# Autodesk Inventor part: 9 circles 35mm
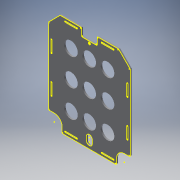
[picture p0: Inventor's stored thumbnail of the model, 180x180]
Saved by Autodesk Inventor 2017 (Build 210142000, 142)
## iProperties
Created: 2014-05
Part Number: 9 circles 35mm
Material: Generic
Document SubType Name: Modeling
Designer: Designer
Density: 1 g/cm^3
Appearance: Default
Author: Designer
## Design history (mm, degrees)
sketch "Sketch1" dims "d120" = 10, "d132" = 10
  geometry: L1 (97.5, 0)-(97.5, 10); L2 (82.5, 10)-(82.5, 0); L3 (17, 40)-(25, 40); L4 (25, 20)-(17, 20); L5 (15, 22)-(15, 38); L6 (195, 214.172)-(195, 22); L7 (158, -15)-(22, -15); L8 (-15, 22)-(-15, 214.172); L9 (-13, 20)-(0, 20); L10 (20, 0)-(20, -13); L11 (160, -13)-(160, 0); L12 (180, 20)-(193, 20); L13 (70, 243)-(70, 227); L14 (72, 225)-(108, 225); L15 (110, 227)-(110, 243); L16 (15, 245)-(-14.414, 215.586); L17 (165.586, 244.414)-(194.414, 215.586); L18 (15, 245)-(68, 245); L19 (112, 245)-(164.172, 245); L20 (27, 38)-(27, 22); C1 r 3 at (90, 220); C2 r 12.5 at (57.5, 177.5); C3 r 12.5 at (122.5, 177.5); C4 r 12.5 at (57.5, 115); C5 r 12.5 at (122.5, 115); C6 r 12.5 at (57.5, 52.5); C7 r 12.5 at (122.5, 52.5); A1 r 7.5 centre (90, 10) between (97.5, 10) and (82.5, 10); A2 r 20 centre (0, 0) between (20, 0) and (0, 20); A3 r 20 centre (180, 0) between (180, 20) and (160, 0); A4 r 7.5 centre (90, 0) between (82.5, 0) and (97.5, 0); A5 r 2 centre (17, 38) between (17, 40) and (15, 38); A6 r 2 centre (25, 22) between (25, 20) and (27, 22); A7 r 2 centre (17, 22) between (15, 22) and (17, 20); A8 r 2 centre (25, 38) between (27, 38) and (25, 40); A9 r 2 centre (68, 243) between (70, 243) and (68, 245); A10 r 2 centre (-13, 214.172) between (-14.414, 215.586) and (-15, 214.172); A11 r 2 centre (72, 227) between (70, 227) and (72, 225); A12 r 2 centre (108, 227) between (108, 225) and (110, 227); A13 r 2 centre (112, 243) between (112, 245) and (110, 243); A14 r 2 centre (164.172, 243) between (165.586, 244.414) and (164.172, 245); A15 r 2 centre (193, 214.172) between (195, 214.172) and (194.414, 215.586); A16 r 2 centre (193, 22) between (193, 20) and (195, 22); A17 r 2 centre (158, -13) between (158, -15) and (160, -13); A18 r 2 centre (22, -13) between (20, -13) and (22, -15); A19 r 2 centre (-13, 22) between (-15, 22) and (-13, 20); 19 further points
  constraints: 40 end point, 38 point on circle, 34 point on line, 34 tangent, 26 centre point, 11 equal radius, 11 perpendicular, 6 parallel, 4 horizontal, 1 vertical, 10 other
  dimensions: "d55" = 260 distance between parallel lines of L7 L19; "d56" = 210 distance between parallel lines of L6 L8; "d107" = 20 distance from line of C1.centre L13; "d111" = 5 distance from line of L14 C1.centre; "d112" = 42.5 vertical distance of C1.centre C2.centre; "d113" = 32.5 horizontal distance of C2.centre C1.centre; "d114" = 25 diameter of C2; "d117" = 65 distance of C2.centre C3.centre; "d125" = 72.5 distance from line of L6 C3.centre; "d126" = 72.5 distance from line of L8 C2.centre (derived); "d129" = 62.5 distance of C2.centre C4.centre; "d134" = 12.5 distance from line of C3.centre L15
extrude "Extrusion1" new body sketch "Sketch1" distance "d69" = 4; taper "d70" = 0 deg
sketch "Sketch2"
  geometry: L1 (30, 24)-(30, 104) reference; L2 (-15, 214.172)-(-15, 22) reference; L3 (68, 245)-(15, 245) reference; L4 (-7.5, 180)-(-7.5, 150); L5 (-9, 180)-(-9, 150); L6 (-6, 150)-(-6, 180); A1 r 1.5 centre (-7.5, 180) between (-6, 180) and (-9, 180); A2 r 1.5 centre (-7.5, 150) between (-9, 150) and (-6, 150); 1 further point
  constraints: 8 end point, 4 point on circle, 4 tangent, 2 centre point, 2 parallel, 1 midpoint
  dimensions: "d72" = 30 distance of L6.start L6.end; "d73" = 3 distance between parallel lines of L6 L5; "d74" = 65 distance from line of L4.start L3; "d75" = 6 distance between parallel lines of L5 L2
extrude "Extrusion2" cut sketch "Sketch2" distance "d76" = 4; taper "d77" = 0 deg
sketch "Sketch3"
  geometry: L1 (82, 22)-(32, 22) reference; L2 (70, 227)-(70, 243) reference; L3 (68, 245)-(15, 245) reference; L4 (28, 237.5)-(58, 237.5); L5 (28, 239)-(58, 239); L6 (58, 236)-(28, 236); A1 r 1.5 centre (28, 237.5) between (28, 239) and (28, 236); A2 r 1.5 centre (58, 237.5) between (58, 236) and (58, 239); 1 further point
  constraints: 8 end point, 4 point on circle, 4 tangent, 2 centre point, 2 parallel, 1 midpoint
  dimensions: "d84" = 3 distance between parallel lines of L5 L6; "d85" = 30 distance of L5.start L5.end; "d86" = 6 distance between parallel lines of L3 L5; "d87" = 12 distance from line of L2 L4.end
extrude "Extrusion3" cut sketch "Sketch3" distance "d88" = 4; taper "d89" = 0 deg
pattern_linear "Rectangular Pattern2" dims "d92" = 94, "d95" = 245
pattern_linear "Rectangular Pattern3" dims "d137" = 195, "d140" = 95
sketch "Sketch7"
  geometry: L1 (186, 55)-(186, 85) reference; L2 (189, 85)-(189, 55) reference; L3 (-9, 55)-(-9, 85) reference; L4 (-6, 85)-(-6, 55) reference; L5 (186, 150)-(186, 180) reference; L6 (189, 180)-(189, 150) reference; L7 (122, -6)-(152, -6) reference; L8 (152, -9)-(122, -9) reference; L9 (28, -6)-(58, -6) reference; L10 (58, -9)-(28, -9) reference; L11 (122, 239)-(152, 239) reference; L12 (152, 236)-(122, 236) reference; L13 (28, 239)-(58, 239) reference; L14 (58, 236)-(28, 236) reference; L15 (-9, 150)-(-9, 180) reference; L16 (-6, 180)-(-6, 150) reference; L17 (82.5, 0)-(82.5, 10) reference; L18 (97.5, 10)-(97.5, 0) reference; L19 (15, 245)-(-14.414, 215.586) reference; L20 (-15, 214.172)-(-15, 22) reference; L21 (-13, 20)-(0, 20) reference; L22 (20, 0)-(20, -13) reference; L23 (22, -15)-(158, -15) reference; L24 (160, -13)-(160, 0) reference; L25 (180, 20)-(193, 20) reference; L26 (195, 22)-(195, 214.172) reference; L27 (194.414, 215.586)-(165.586, 244.414) reference; L28 (164.172, 245)-(112, 245) reference; L29 (110, 243)-(110, 227) reference; L30 (108, 225)-(72, 225) reference; L31 (70, 227)-(70, 243) reference; L32 (68, 245)-(15, 245) reference; C1 r 3 at (90, 220) reference; A1 r 1.5 centre (187.5, 55) between (186, 55) and (189, 55) reference; A2 r 1.5 centre (187.5, 85) between (189, 85) and (186, 85) reference; A3 r 1.5 centre (-7.5, 55) between (-9, 55) and (-6, 55) reference; A4 r 1.5 centre (-7.5, 85) between (-6, 85) and (-9, 85) reference; A5 r 1.5 centre (187.5, 150) between (186, 150) and (189, 150) reference; A6 r 1.5 centre (187.5, 180) between (189, 180) and (186, 180) reference; A7 r 1.5 centre (122, -7.5) between (122, -6) and (122, -9) reference; A8 r 1.5 centre (152, -7.5) between (152, -9) and (152, -6) reference; A9 r 1.5 centre (28, -7.5) between (28, -6) and (28, -9) reference; A10 r 1.5 centre (58, -7.5) between (58, -9) and (58, -6) reference; A11 r 1.5 centre (122, 237.5) between (122, 239) and (122, 236) reference; A12 r 1.5 centre (152, 237.5) between (152, 236) and (152, 239) reference; A13 r 1.5 centre (28, 237.5) between (28, 239) and (28, 236) reference; A14 r 1.5 centre (58, 237.5) between (58, 236) and (58, 239) reference; A15 r 1.5 centre (-7.5, 150) between (-9, 150) and (-6, 150) reference; A16 r 1.5 centre (-7.5, 180) between (-6, 180) and (-9, 180) reference; A17 r 7.5 centre (90, 10) between (97.5, 10) and (82.5, 10) reference; A18 r 7.5 centre (90, 0) between (82.5, 0) and (97.5, 0) reference; A19 r 2 centre (-13, 214.172) between (-14.414, 215.586) and (-15, 214.172) reference; A20 r 2 centre (-13, 22) between (-15, 22) and (-13, 20) reference; A21 r 20 centre (0, 0) between (20, 0) and (0, 20) reference; A22 r 2 centre (22, -13) between (20, -13) and (22, -15) reference; A23 r 2 centre (158, -13) between (158, -15) and (160, -13) reference; A24 r 20 centre (180, 0) between (180, 20) and (160, 0) reference; A25 r 2 centre (193, 22) between (193, 20) and (195, 22) reference; A26 r 2 centre (193, 214.172) between (195, 214.172) and (194.414, 215.586) reference; A27 r 2 centre (164.172, 243) between (165.586, 244.414) and (164.172, 245) reference; A28 r 2 centre (112, 243) between (112, 245) and (110, 243) reference; A29 r 2 centre (108, 227) between (108, 225) and (110, 227) reference; A30 r 2 centre (72, 227) between (70, 227) and (72, 225) reference; A31 r 2 centre (68, 243) between (70, 243) and (68, 245) reference
sketch "Sketch8"
  geometry: L1 (68, 245)-(15, 245) reference; C1 r 17.5 at (90, 115); C2 r 17.5 at (43, 115); C3 r 17.5 at (137, 115); C4 r 3 at (90, 220) reference; C5 r 17.5 at (90, 45); C6 r 17.5 at (43, 45); C7 r 17.5 at (137, 45); C8 r 17.5 at (90, 185); C9 r 17.5 at (43, 185); C10 r 17.5 at (137, 185); 1 further point
  constraints: 9 centre point, 6 horizontal alignment, 3 vertical alignment
  dimensions: "d167" = 35 diameter of C1; "d169" = 35 diameter of C2; "d172" = 35 diameter of C3; "d174" = 47 distance of C1.centre C2.centre; "d175" = 47 distance of C3.centre C1.centre; "d176" = 130 distance from line of C2.centre L1; "d177" = 35 diameter of C5; "d178" = 35 diameter of C6; "d179" = 35 diameter of C7; "d180" = 47 distance of C5.centre C6.centre; "d181" = 47 distance of C7.centre C5.centre; "d182" = 70 distance of C6.centre C2.centre; "d183" = 35 diameter of C8; "d184" = 35 diameter of C9; "d185" = 35 diameter of C10; "d186" = 47 distance of C8.centre C9.centre; "d187" = 47 distance of C10.centre C8.centre; "d188" = 70 distance of C2.centre C9.centre
extrude "Extrusion5" cut sketch "Sketch8" stored distance "d189" = 10; taper "d190" = 0 deg
body "Solid1"
feature "耀䀸"
